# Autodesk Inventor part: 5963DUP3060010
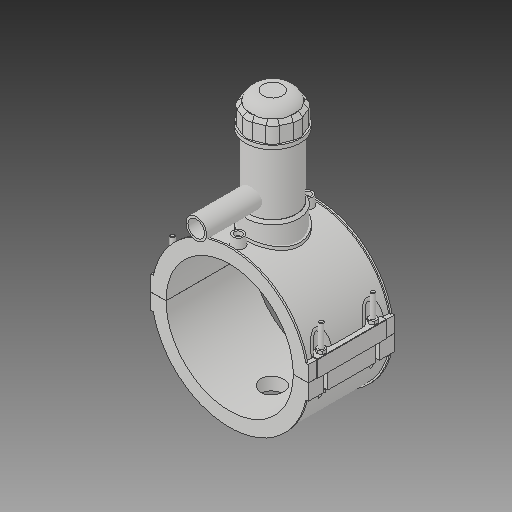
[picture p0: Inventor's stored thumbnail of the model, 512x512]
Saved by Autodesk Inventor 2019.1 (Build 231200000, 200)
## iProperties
Created: 2017-07
Part Number: 5963DUP3060010
Material: Generic
Description: PLASSON TAPPING SADDLE 6''DIPS x 1''CTS
Document SubType Name: Modeling
Designer: KIM
Density: 1 g/cm^3
Appearance: Default
Author: KIM
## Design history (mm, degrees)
derived "5963DBP_5963BUP.ipt"
feature "Solid1::5963DBP_5963BUP.ipt"
feature "Solid2::5963DBP_5963BUP.ipt"
feature "Solid3::5963DBP_5963BUP.ipt"
tag "TaggingFeature1"
body "Solid1"
body "Solid2"
body "Solid3"
other parameters: "d0" = 174.5, "d2" = 215.9, "d3" = 43.625, "d4" = 118.11, "d5" = 0, "d6" = 0.1, "d8" = 0, "d19" = 6, "d20" = 6, "d21" = 70.866, "d23" = 0, "d24" = 35.433, "d26" = 0, "d27" = 3, "d28" = 3, "d29" = 3, "d30" = 58.16667, "d31" = 6, "d32" = 0, "d33" = 0, "d34" = 0.6, "d40" = 108.888, "d41" = 75.035, "d43" = 0, "d45" = 0, "d47" = 175.566, "d70" = 15, "d72" = 0, "d73" = 6, "d75" = 5, "d76" = 0, "d77" = 8.725, "d78" = 117.25, "d79" = 15, "d80" = 47.244, "d82" = 5 deg, "d84" = 4, "d85" = 14, "d86" = 0, "d87" = 3, "d88" = 0, "d89" = 1, "d90" = 1, "d91" = 94.488, "d92" = 0, "d93" = 0.5, "d94" = 91.84211, "d96" = 213.588, "d97" = 2.3622, "d98" = 0, "d120" = 140 deg, "d121" = 24.228, "d122" = 20 deg, "d123" = 418.8, "d124" = 125.64, "d126" = 0, "d143" = 179.735, "d145" = 26.84615, "d149" = 2.6175, "d150" = 29.53077, "d153" = 118.11, "d154" = 0, "d156" = 104.7, "d157" = 160 deg, "d159" = 6.98, "d161" = 2.6175, "d162" = 70.866, "d163" = 0, "d164" = 87.25, "d167" = 17.45, "d168" = 102.14634, "d170" = 3.4335, "d172" = 0, "d173" = 1, "d175" = 87.25, "d176" = 20 deg, "d177" = 12.215, "d178" = 34.9, "d180" = 0, "d183" = 13.96, "d184" = 9.772, "d185" = 38.38575, "d186" = 38.38575, "d187" = 104.7, "d188" = 10.47, "d189" = 12.215, "d190" = 0, "d191" = 157.05, "d193" = 7.3248, "d194" = 4.13385, "d195" = 90 deg, "d197" = 0, "d199" = 0, "d200" = 17.45, "d202" = 0, "d203" = 177.038, "d204" = 71.28325, "d205" = 52.5245, "d206" = 63.77975, "d207" = 132.7785, "d208" = 138.08964, "d209" = 164.64534, "d210" = 64.5301, "d211" = 75.035, "d212" = 60.028, "d213" = 45.7191, "d216" = 0, "d217" = 17.45, "d218" = 17.45, "d219" = 3.49, "d222" = 174.5, "d224" = 0, "d225" = 65.024, "d226" = 28.45, "d227" = 22.76, "d228" = 104.902, "d230" = 5.235, "d_" = 174.5, "B_" = 215.9, "L_" = 118.11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
